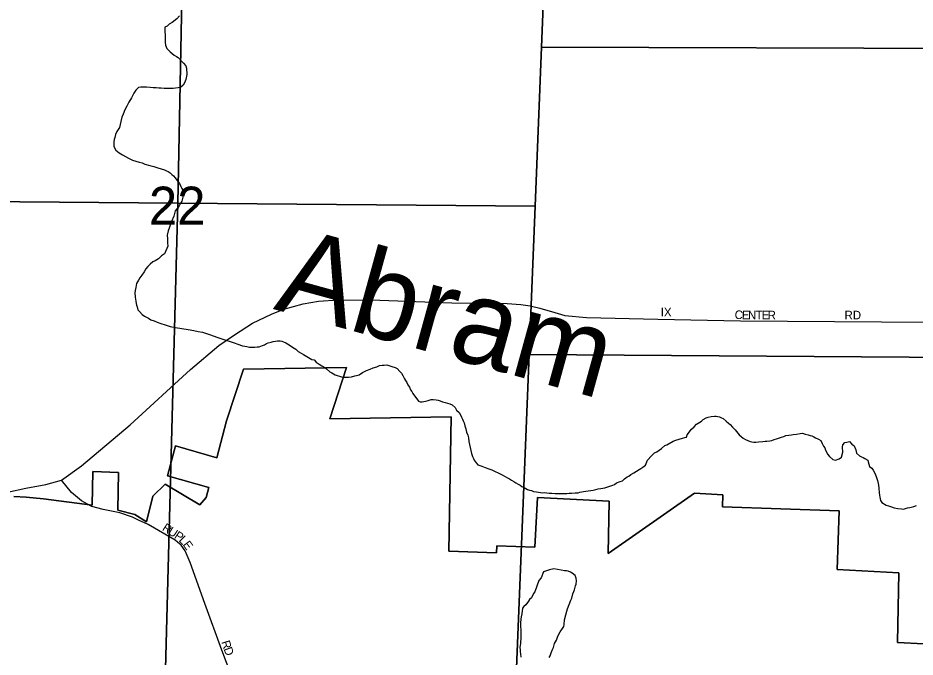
# Model space of a CAD drawing. Extents: x 2010165 to 2382125, y 1060529 to 1407316.
# Drawn here: x 2140939 to 2146157, y 1235726 to 1239445 of the extents above; entities that cross this region are included whole.
import ezdxf

# ---------------------------------------------------------------- set-up
doc = ezdxf.new("R2010")
doc.units = 0
for name, color, linetype in [('GM_X_City_Street', 7, 'Continuous'), ('GM_X_City_Street_Text', 7, 'Continuous'), ('GM_X_Corporation', 7, 'Continuous'), ('GM_X_Minor_Lake', 7, 'Continuous'), ('GM_X_Minor_River', 7, 'Continuous'), ('GM_X_Minor_River_Text', 7, 'Continuous'), ('GM_X_Section', 7, 'Continuous'), ('GM_X_Section_Text', 7, 'Continuous')]:
    doc.layers.add(name, color=color, linetype=linetype)

msp = doc.modelspace()

# ---------------------------------------------------------------- linework, layer by layer
at = {"layer": 'GM_X_City_Street'}
for points in [[(2140878.5, 1236685.7), (2140984.3, 1236707.9), (2141101.4, 1236729.4), (2141191.8, 1236755.2), (2141309.2, 1236839.4), (2141591.1, 1237078.3), (2141942.3, 1237398.6), (2142107.2, 1237539.6), (2142198, 1237601.7), (2142303.1, 1237668.7), (2142413, 1237721.2), (2142484.7, 1237750.1), (2142598.8, 1237782.4), (2142686.2, 1237797.6), (2142802.2, 1237805.2), (2143043.5, 1237803.3), (2143462, 1237787.6), (2143784.6, 1237783.2), (2143864.8, 1237777.2), (2143918.4, 1237769.6), (2143974.8, 1237756.4), (2144062.5, 1237731.1), (2144119, 1237713.3), (2144245.4, 1237701.4), (2144660.8, 1237692.8)], [(2144660.8, 1237692.8), (2145141.7, 1237682.9), (2146781.9, 1237671), (2146895.9, 1237673.3)], [(2141343.7, 1236615.9), (2141309.1, 1236635), (2141250.1, 1236683.8), (2141191.8, 1236755.2)], [(2141492.9, 1236573.1), (2141435.2, 1236584.1), (2141368.1, 1236602.4), (2141343.7, 1236615.9)], [(2141640.2, 1236523.1), (2141606, 1236539.4), (2141530.8, 1236565.8), (2141492.9, 1236573.1)], [(2141866.2, 1236394.9), (2141852.8, 1236406), (2141695.5, 1236496.7), (2141640.2, 1236523.1)], [(2142215.9, 1235531), (2142179.9, 1235622.2), (2142124.6, 1235766.7), (2142026.7, 1236037), (2141940.2, 1236277), (2141912, 1236344.5), (2141888.2, 1236376.8), (2141866.2, 1236394.9)]]:
    msp.add_lwpolyline(points, dxfattribs=at)
at = {"layer": 'GM_X_Corporation'}
for points in [[(2140915.9, 1236660.8), (2140986.6, 1236657.1), (2141088, 1236646.4), (2141370.4, 1236610.2), (2141373.8, 1236805.1), (2141523.7, 1236799.9), (2141519.9, 1236580), (2141618.9, 1236555.3), (2141686.7, 1236512.9), (2141724, 1236662.3), (2141794.7, 1236733), (2141996.1, 1236612), (2142032.9, 1236654.3), (2142048.4, 1236712.2), (2141808.1, 1236781.1), (2141854.7, 1236955), (2142095, 1236886.1), (2142152.7, 1237101.5), (2142250, 1237401.1), (2142849.9, 1237411.5), (2142752.6, 1237112), (2143459.5, 1237124.3), (2143445.8, 1236342.4), (2143722.7, 1236332.8), (2143723.4, 1236372.8), (2143946.2, 1236365), (2143961.4, 1236654.6), (2144377.8, 1236632.7), (2144372.5, 1236327.8), (2144874.7, 1236679.4), (2145038.4, 1236670.8), (2145036, 1236600.9), (2145715.6, 1236577.1), (2145703.6, 1236235.3), (2146062.1, 1236216.5), (2146055.1, 1235811.6), (2146361.7, 1235795.5)], [(2146361.7, 1235795.5), (2146055.1, 1235811.6), (2146062.1, 1236216.5), (2145703.6, 1236235.3), (2145715.6, 1236577.1), (2145036, 1236600.9), (2145038.4, 1236670.8), (2144874.7, 1236679.4), (2144372.5, 1236327.8), (2144377.8, 1236632.7), (2143961.4, 1236654.6), (2143946.2, 1236365), (2143723.4, 1236372.8), (2143722.7, 1236332.8), (2143445.8, 1236342.4), (2143459.5, 1237124.3), (2142752.6, 1237112), (2142849.9, 1237411.5), (2142250, 1237401.1), (2142152.7, 1237101.5), (2142095, 1236886.1), (2141854.7, 1236955), (2141808.1, 1236781.1), (2142048.4, 1236712.2), (2142032.9, 1236654.3), (2141996.1, 1236612), (2141794.7, 1236733), (2141724, 1236662.3), (2141686.7, 1236512.9), (2141618.9, 1236555.3), (2141519.9, 1236580), (2141523.7, 1236799.9), (2141373.8, 1236805.1), (2141370.4, 1236610.2), (2141088, 1236646.4), (2140986.6, 1236657.1), (2140915.9, 1236660.8)]]:
    msp.add_lwpolyline(points, dxfattribs=at)
at = {"layer": 'GM_X_Minor_Lake'}
for points in [[(2144120, 1236227.4), (2144055.2, 1236240.2), (2144031.2, 1236233.7), (2144019.2, 1236229.5), (2144007.3, 1236225.2), (2143995.3, 1236221), (2143981.9, 1236186.6), (2143968.1, 1236172.3), (2143956.7, 1236138), (2143945.3, 1236105.6), (2143937.4, 1236095.5), (2143925.8, 1236071.2), (2143914, 1236060.9), (2143908.2, 1236050.8), (2143892.5, 1236030.4), (2143880.6, 1236020.1), (2143872.8, 1236009.9), (2143869.4, 1235977.8), (2143865.7, 1235959.6), (2143864, 1235945.6), (2143862.3, 1235925.4), (2143862.7, 1235903.4), (2143863.1, 1235885.3), (2143863.4, 1235865.3), (2143863.9, 1235841.2), (2143862.6, 1235805.1), (2143859, 1235780.9), (2143859.2, 1235768.9), (2143859.4, 1235756.8), (2143861.7, 1235744.8), (2143864, 1235724.8)], [(2144028.6, 1235723.9), (2144034.4, 1235734.1), (2144038.3, 1235744.2), (2144045.9, 1235766.4), (2144053.6, 1235782.6), (2144059.2, 1235804.8), (2144070.9, 1235825.1), (2144078.5, 1235847.3), (2144092.1, 1235873.7), (2144105.8, 1235892), (2144113.6, 1235904.2), (2144115.3, 1235916.2), (2144118.9, 1235942.4), (2144126.3, 1235972.6), (2144132, 1235992.8), (2144135.7, 1236006.9), (2144154.9, 1236057.5), (2144160.7, 1236069.6), (2144166.2, 1236093.8), (2144172, 1236108), (2144175.8, 1236118.1), (2144181.4, 1236140.3), (2144185.3, 1236150.4), (2144186.9, 1236170.5), (2144186.6, 1236184.5), (2144180.3, 1236200.5), (2144162, 1236214.1), (2144151.9, 1236220), (2144139.7, 1236225.8), (2144129.6, 1236227.6), (2144117.6, 1236227.3), (2144117.6, 1236227.3)]]:
    msp.add_lwpolyline(points, dxfattribs=at)
at = {"layer": 'GM_X_Minor_River'}
for points in [[(2141878.4, 1239457.5), (2141862.6, 1239439.1), (2141836.9, 1239418.6), (2141819.1, 1239408.2), (2141807.2, 1239397.9)], [(2141807.2, 1239397.9), (2141793.3, 1239391.7), (2141793.6, 1239375.6), (2141794.3, 1239335.5), (2141794.9, 1239303.4), (2141797.2, 1239287.4), (2141801.4, 1239277.4), (2141805.6, 1239267.5), (2141813.8, 1239257.6), (2141824, 1239247.8), (2141836.3, 1239238), (2141848.5, 1239228.2), (2141860.7, 1239220.4), (2141870.8, 1239214.5), (2141901.5, 1239181), (2141915.8, 1239167.2), (2141920.1, 1239153.3), (2141920.8, 1239115.2), (2141915.3, 1239087), (2141907.7, 1239066.8), (2141899.9, 1239054.6), (2141884.1, 1239040.2), (2141842, 1239035.4), (2141811.9, 1239034.8), (2141789.9, 1239034.4), (2141771.8, 1239036.1), (2141757.7, 1239035.8), (2141743.7, 1239037.5), (2141725.6, 1239039.2), (2141707.5, 1239040.8), (2141687.4, 1239042.5), (2141669.3, 1239042.1), (2141653.3, 1239041.8), (2141639.3, 1239039.5), (2141625.5, 1239025.2), (2141613.8, 1239006.9), (2141600.2, 1238980.6), (2141584.7, 1238954.2), (2141573, 1238931.9), (2141561.4, 1238909.6), (2141551.8, 1238885.3), (2141544.1, 1238867.1), (2141536.6, 1238842.9), (2141529.2, 1238806.6), (2141513.6, 1238784.3), (2141505.9, 1238766.1), (2141502.2, 1238749.9), (2141498.4, 1238737.8), (2141496.6, 1238723.7), (2141496.9, 1238709.7), (2141497.1, 1238699.7), (2141501.3, 1238689.7), (2141507.6, 1238675.8), (2141527.9, 1238660.1), (2141546.2, 1238648.4), (2141582.7, 1238629.1), (2141605, 1238617.4), (2141625.1, 1238611.8), (2141643.3, 1238606.1), (2141661.4, 1238602.5), (2141677.6, 1238594.8), (2141705.9, 1238587.3), (2141730.1, 1238579.7), (2141752.3, 1238572.1), (2141772.5, 1238566.5), (2141790.6, 1238560.8), (2141802.8, 1238555), (2141812.9, 1238551.2), (2141825.1, 1238543.4), (2141833.3, 1238533.5), (2141843.5, 1238525.7), (2141853.7, 1238513.8), (2141864, 1238502), (2141870.2, 1238492.1), (2141878.4, 1238482.2), (2141886.7, 1238464.3), (2141893, 1238452.4), (2141897.2, 1238442.4), (2141899.4, 1238430.4), (2141899.6, 1238418.4), (2141897.9, 1238402.3), (2141892.4, 1238378.1), (2141882.6, 1238363.9), (2141876.8, 1238351.7), (2141865.1, 1238335.5), (2141853.2, 1238323.2), (2141845.8, 1238290.9), (2141832.3, 1238260.6), (2141820.9, 1238228.2), (2141813.3, 1238206), (2141807.7, 1238181.8), (2141808.1, 1238159.8), (2141808.6, 1238135.7), (2141810.9, 1238117.7), (2141791.6, 1238073.2), (2141773.8, 1238060.8), (2141756.1, 1238042.4), (2141736.2, 1238032), (2141724.3, 1238025.7), (2141708.5, 1238011.4), (2141694.7, 1237999.1)], [(2141694.7, 1237999.1), (2141682.9, 1237984.8), (2141673.2, 1237968.6), (2141659.5, 1237948.2), (2141647.8, 1237931.9), (2141640, 1237919.8), (2141634.1, 1237909.6), (2141628.3, 1237899.5), (2141624.7, 1237877.3), (2141621, 1237859.2), (2141619.3, 1237845.1), (2141621.7, 1237821.1), (2141624.2, 1237797), (2141626.5, 1237783), (2141628.7, 1237773), (2141632.9, 1237763.1), (2141637.2, 1237747.1), (2141645.4, 1237737.2), (2141661.7, 1237719.5), (2141676, 1237709.7), (2141686.1, 1237703.9), (2141698.3, 1237698.1), (2141712.5, 1237688.3), (2141730.7, 1237682.7), (2141748.9, 1237675), (2141769.1, 1237667.4), (2141795.3, 1237659.8), (2141823.6, 1237650.3), (2141855.8, 1237642.9), (2141892, 1237637.6), (2141928.3, 1237632.3), (2141962.5, 1237626.9), (2141986.7, 1237621.4), (2142012.8, 1237615.8), (2142035.1, 1237608.2), (2142053.2, 1237602.6), (2142101.7, 1237585.4), (2142119.9, 1237579.8), (2142142.1, 1237572.2), (2142168.3, 1237564.6), (2142196.6, 1237555.1), (2142218.8, 1237547.6), (2142245.1, 1237538), (2142259.2, 1237534.3), (2142269.3, 1237532.5), (2142285.4, 1237528.8), (2142295.4, 1237528.9), (2142307.4, 1237529.2), (2142317.5, 1237529.4), (2142329.5, 1237531.6), (2142341.5, 1237531.8), (2142361.5, 1237538.2), (2142373.4, 1237542.5), (2142385.3, 1237550.7), (2142395.3, 1237554.9), (2142411.2, 1237559.3), (2142423.2, 1237561.5), (2142437.2, 1237563.8), (2142449.2, 1237566), (2142463.3, 1237566.3), (2142473.4, 1237564.5), (2142483.5, 1237560.6), (2142497.6, 1237554.9), (2142515.9, 1237543.2), (2142536.2, 1237529.6), (2142554.5, 1237517.9), (2142568.8, 1237504.1), (2142587, 1237494.4), (2142599.2, 1237486.6), (2142609.4, 1237480.8), (2142619.5, 1237475), (2142629.6, 1237469.1), (2142647.9, 1237457.4), (2142662, 1237455.7), (2142674.3, 1237441.9), (2142690.6, 1237430.2), (2142706.8, 1237420.4), (2142723, 1237410.7), (2142733.2, 1237402.9), (2142753.6, 1237385.2), (2142763.8, 1237379.4), (2142773.9, 1237373.6), (2142784, 1237367.7), (2142820.4, 1237356.4), (2142834.4, 1237354.6), (2142852.5, 1237355), (2142862.5, 1237355.2), (2142878.5, 1237357.5), (2142898.5, 1237361.9), (2142908.5, 1237364.1), (2142924.5, 1237368.4), (2142942.3, 1237382.8), (2142966.2, 1237393.3), (2142988.1, 1237401.8), (2143006, 1237408.1), (2143026, 1237414.5), (2143041.9, 1237422.8), (2143057.9, 1237425.2), (2143069.9, 1237425.4), (2143084, 1237425.7), (2143096.1, 1237421.9)], [(2143096.1, 1237421.9), (2143114.2, 1237416.2), (2143132.4, 1237410.5), (2143144.6, 1237404.7), (2143160.9, 1237387), (2143169.2, 1237377.1), (2143177.4, 1237365.2), (2143187.8, 1237345.4), (2143194, 1237335.5), (2143200.3, 1237323.5), (2143206.5, 1237309.6), (2143216.8, 1237295.8), (2143223.1, 1237281.8), (2143229.3, 1237271.9), (2143235.5, 1237260), (2143268.5, 1237214.5), (2143278.6, 1237210.6), (2143290.6, 1237210.9), (2143308.6, 1237215.2), (2143324.6, 1237219.6), (2143342.6, 1237223.9), (2143354.6, 1237224.1), (2143370.7, 1237222.5), (2143382.8, 1237220.7), (2143394.9, 1237216.9), (2143409, 1237211.1), (2143423.2, 1237207.4), (2143437.3, 1237203.7), (2143451.4, 1237199.9), (2143465.5, 1237194.2), (2143481.9, 1237178.4), (2143490.2, 1237162.5), (2143504.5, 1237148.8), (2143512.8, 1237134.9), (2143519, 1237122.9), (2143525.3, 1237111), (2143529.5, 1237101.1), (2143533.7, 1237089.1), (2143538.1, 1237071.1), (2143544.4, 1237053.2), (2143548.8, 1237035.2), (2143555.1, 1237017.3), (2143559.4, 1237001.3), (2143561.8, 1236981.3), (2143566.1, 1236963.3), (2143568.5, 1236945.3), (2143572.8, 1236927.3), (2143577.1, 1236911.3), (2143583.5, 1236893.4), (2143587.7, 1236881.4), (2143591.9, 1236871.5), (2143604.3, 1236855.7), (2143614.5, 1236843.8), (2143636.7, 1236836.2), (2143656.9, 1236828.6), (2143677.1, 1236820.9), (2143695.3, 1236815.3), (2143752, 1236788.3), (2143772.3, 1236776.6), (2143786.5, 1236768.9), (2143798.6, 1236763.1), (2143808.8, 1236755.2), (2143823, 1236747.5), (2143835.2, 1236739.7), (2143849.4, 1236731.9), (2143859.5, 1236726.1), (2143869.7, 1236718.3), (2143883.9, 1236712.5), (2143902.1, 1236700.8), (2143914.2, 1236697.1), (2143926.3, 1236695.3), (2143938.5, 1236689.5), (2143954.5, 1236687.8), (2143966.6, 1236686), (2143978.7, 1236684.2), (2143990.8, 1236682.5), (2144002.8, 1236682.7), (2144014.9, 1236680.9), (2144029, 1236679.2), (2144045, 1236679.5), (2144063.1, 1236677.8), (2144083.2, 1236678.2), (2144105.2, 1236678.6), (2144131.3, 1236677.1), (2144145.3, 1236679.4), (2144159.4, 1236679.7), (2144179.4, 1236682.1), (2144197.5, 1236682.4), (2144207.5, 1236684.6), (2144219.4, 1236686.8), (2144229.4, 1236689.1), (2144241.4, 1236691.3), (2144255.5, 1236693.6), (2144271.5, 1236695.9), (2144285.5, 1236698.1), (2144299.5, 1236700.4), (2144313.4, 1236704.7), (2144329.4, 1236707), (2144341.4, 1236709.2), (2144353.4, 1236711.5), (2144387.4, 1236722.2)], [(2144387.4, 1236722.2), (2144399.3, 1236726.4), (2144409.3, 1236730.6), (2144421.2, 1236738.9), (2144441.1, 1236747.3), (2144455.1, 1236751.6), (2144466.9, 1236763.8), (2144482.7, 1236774.2), (2144492.7, 1236778.4), (2144504.5, 1236788.6), (2144520.4, 1236799), (2144536.3, 1236807.3), (2144552.2, 1236817.6), (2144562.1, 1236823.9), (2144574, 1236830.1), (2144589.8, 1236842.4), (2144601.3, 1236870.8), (2144624.9, 1236897.3), (2144640.7, 1236913.7), (2144654.6, 1236919.9), (2144668.5, 1236930.3), (2144682.3, 1236940.6), (2144702.1, 1236957), (2144714, 1236961.2), (2144749.8, 1236982), (2144765.7, 1236988.3), (2144785.7, 1236994.7), (2144803.6, 1236999.1), (2144817.6, 1237003.3), (2144827.6, 1237005.5), (2144831.4, 1237019.7), (2144856.9, 1237052.3), (2144872.6, 1237066.6), (2144886.4, 1237080.9), (2144904.3, 1237093.3), (2144914.2, 1237099.5), (2144924, 1237107.7), (2144941.9, 1237118.1), (2144953.9, 1237122.3), (2144971.9, 1237126.7), (2144989.9, 1237127.1), (2144999.9, 1237127.2), (2145010, 1237125.4), (2145020.1, 1237123.6), (2145030.2, 1237117.8), (2145040.3, 1237114), (2145058.7, 1237098.3), (2145070.9, 1237086.5), (2145081.1, 1237078.6), (2145095.5, 1237062.9), (2145109.8, 1237049.1), (2145134.4, 1237019.4), (2145144.6, 1237009.6), (2145156.8, 1236999.8), (2145171, 1236992.1), (2145185.2, 1236986.3), (2145197.3, 1236980.5), (2145207.4, 1236978.7), (2145219.5, 1236976.9), (2145231.5, 1236977.2), (2145245.5, 1236979.4), (2145271.6, 1236979.9), (2145285.6, 1236982.2), (2145295.6, 1236982.4), (2145311.6, 1236984.7), (2145323.6, 1236987), (2145337.6, 1236991.2), (2145351.6, 1236995.5), (2145363.5, 1236999.8), (2145379.5, 1237006.1), (2145393.4, 1237010.4), (2145405.4, 1237014.6), (2145423.4, 1237017), (2145437.4, 1237019.2), (2145447.4, 1237021.4), (2145467.4, 1237023.8), (2145489.5, 1237026.3), (2145501.5, 1237028.5), (2145517.6, 1237022.8), (2145535.7, 1237019.1), (2145545.9, 1237015.3), (2145555.9, 1237013.5), (2145568.1, 1237007.7), (2145578.2, 1237001.9), (2145594.4, 1236994.1), (2145608.6, 1236986.4), (2145617, 1236968.5), (2145625.3, 1236952.6), (2145631.5, 1236942.7), (2145635.7, 1236930.7), (2145644, 1236916.8), (2145648.2, 1236906.9), (2145658.5, 1236893), (2145678.9, 1236875.4), (2145695, 1236871.7), (2145714.9, 1236880.1), (2145728.8, 1236888.4), (2145736.3, 1236918.6), (2145735.8, 1236946.7), (2145737.5, 1236960.8), (2145749.3, 1236975.1)], [(2145749.3, 1236975.1), (2145759.3, 1236977.2), (2145775.3, 1236979.6), (2145789.6, 1236965.8), (2145801.8, 1236956), (2145812.3, 1236932.1), (2145816.7, 1236912.1), (2145833, 1236896.4), (2145845.2, 1236890.6), (2145855.3, 1236886.8), (2145865.4, 1236880.9), (2145881.6, 1236871.2), (2145883.8, 1236861.2), (2145892.3, 1236835.3), (2145904.6, 1236825.5), (2145912.8, 1236813.6), (2145923.2, 1236795.8), (2145931.6, 1236775.9), (2145938, 1236753.9), (2145942.4, 1236735.9), (2145944.5, 1236725.9), (2145946.9, 1236707.9), (2145947.4, 1236681.8), (2145949.6, 1236667.8), (2145951.9, 1236655.8), (2145956.2, 1236637.9), (2145964.5, 1236626), (2145988.8, 1236610.4), (2146002.9, 1236606.6), (2146019.1, 1236600.9), (2146035.3, 1236595.2), (2146057.4, 1236589.6), (2146077.5, 1236588), (2146089.6, 1236586.2), (2146113.5, 1236594.7), (2146127.5, 1236597), (2146149.5, 1236601.4), (2146165.5, 1236607.8)]]:
    msp.add_lwpolyline(points, dxfattribs=at)
at = {"layer": 'GM_X_Section'}
for points in [[(2141922.4, 1241143.5), (2141869.6, 1238367.9), (2139800.3, 1238385.2), (2139842.1, 1240542.5), (2139854.6, 1241162.3)], [(2144057.8, 1241124.1), (2143983.7, 1239275.5), (2143946.6, 1238350.5), (2141869.6, 1238367.9), (2141922.4, 1241143.5)], [(2146579.7, 1241102), (2146484.2, 1239266.4), (2143983.7, 1239275.5), (2144057.8, 1241124.1)], [(2146484.2, 1239266.4), (2146397.7, 1237469.6), (2143912, 1237485.9), (2143946.6, 1238350.5), (2143983.7, 1239275.5)], [(2141869.6, 1238367.9), (2141797.8, 1235658.1), (2139732.4, 1235654), (2139740.6, 1235952.8), (2139795.1, 1238150), (2139800.3, 1238385.2)], [(2143946.6, 1238350.5), (2143912, 1237485.9), (2143838.9, 1235662.2), (2141797.8, 1235658.1), (2141869.6, 1238367.9)], [(2143912, 1237485.9), (2146397.7, 1237469.6), (2146311, 1235667.1), (2143838.9, 1235662.2)]]:
    msp.add_lwpolyline(points, close=True, dxfattribs=at)

# ---------------------------------------------------------------- texts
at = {"layer": 'GM_X_City_Street_Text'}
for s, rotation, p in [('IX', 0, (2144677.5, 1237708.5)), ('C', 354.8693, (2145105.6, 1237695.3)), ('E', 359.1344, (2145149.1, 1237691.5)), ('N', 359.9533, (2145185.1, 1237691)), ('T', 359.9956, (2145229.1, 1237691)), ('E', 359.9956, (2145264.3, 1237691)), ('R', 0, (2145299.5, 1237691)), ('RD', 0, (2145746.7, 1237691)), ('R', 327.1721, (2141774, 1236466.4)), ('U', 327.1726, (2141807.3, 1236444.9)), ('P', 325.825, (2141844, 1236421.3)), ('L', 315.1063, (2141871.2, 1236403)), ('E', 306.2252, (2141894.8, 1236379.8)), ('R', 287.4018, (2142121.4, 1235814.1)), ('D', 290.7182, (2142134.2, 1235773.4))]:
    msp.add_text(s, height=50, rotation=rotation, dxfattribs=at).set_placement(p)
at = {"layer": 'GM_X_Minor_River_Text'}
msp.add_text('Abram', height=500.29, rotation=344.5784, dxfattribs=at).set_placement((2142420, 1237752))
at = {"layer": 'GM_X_Section_Text'}
msp.add_text('22', height=221, rotation=0, dxfattribs=at).set_placement((2141700.9, 1238242.3))

doc.saveas('drawing.dxf')
